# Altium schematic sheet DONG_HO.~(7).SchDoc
size A
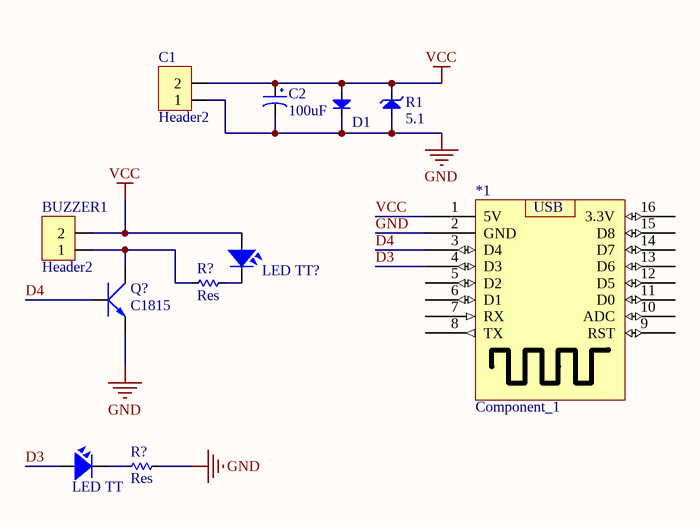
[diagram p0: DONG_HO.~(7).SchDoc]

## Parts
(Parts that share a designator on the sheet are numbered #1, #2 ... from top to bottom, then left to right.)
*1  Component_1  [ESP WEMOS MINI]
BUZZER1  Header2  [Header2]
C1  Header2  [Header2]
C2  100uF  [CP1/2.5]
D1  Diode  [DIO-1A-SMALL]  (value not drawn)
LED_TT  LED  [LED-3MM-YELLOW]  (value not drawn)
LED_TT?  LED  [LED-3MM-YELLOW]  (value not drawn)
Q?  C1815  [QTO-92]
R1  5.1  [DIO-1A-ZEN]
R?#1  Res  [RES-1/8W-SMALL]
R?#2  Res  [RES-1/8W-SMALL]

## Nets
GND: *1.2(GND) C1.1 C2.2 D1.2(K) Q?.1(E) R1.1(A) R?#2.2
VCC: *1.1(5V) BUZZER1.2 C1.2 C2.1 D1.1(A) LED_TT?.1 R1.2(K)
D3: *1.4(D3) LED_TT.1
D4: *1.3(D4) Q?.3(B)
NetBUZZER1_1: BUZZER1.1 Q?.2(C) R?#1.1
NetLED_TT?_2: LED_TT?.2 R?#1.2
NetLED_TT_2: LED_TT.2 R?#2.1

Not connected (* = marked no-connect by the designer): *1 5(D2) 6(D1) 7(RX) 8(TX) 9(RST) 10(ADC) 11(D0) 12(D5) 13(D6) 14(D7) 15(D8) 16(3.3V)

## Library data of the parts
BUZZER1 C1 = Header2: Header IDC, 2 x 1 Pin Vertical 2.54mm Pitch (Non-Boxed, Male); Manufacturer: W¨¹rth Elektronik eiSos GmbH; partNo: 613002143121; ComponentLink1 Description: Manufacturer; ComponentLink2 Description: Datasheet; NoPins: 02
C2 = CP2: C 47uF/50V , 220uF/16V; Value: 47uF/16 - 50V; Description 1: 470uF/6,3V - 330uF/10V - 220uF/16V; Description 2: 100uF/25V - 35V - 47uF/50V - 22uF/100V; Description 3: 33uF => 47uF/63V - 1uF => 4,7uF/160V; Description 4: 1uF => 2,2uF/250V - 1uF/350V
D1 = Diode: Default Diode; Code - JEDEC: DO-214-AB; Value: 1N5007
LED_TT LED_TT? = LED: LED Single colour Green and Red; Value: LED 3 ly Single Colour
Q? = C1815: NPN 600mW, ECB
R1 = DIODE Zener: Zenner
R?#1 R?#2 = Res: Manufacturer: Generic Components; Class: Passive; SubClass: R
